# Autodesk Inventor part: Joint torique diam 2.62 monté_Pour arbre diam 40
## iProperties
Shininess: 64.0
Length Units: 11269
Angle Units: 11279
Time Units: 11290
Mass Units: 11283
Length Display Precision: 3
Angle Display Precision: 2
Compacted: True
Part Number: Joint torique diam 2.62 monté_Pour arbre diam 40
Document SubType Name: Modeling
Created: 2006-01
Material: Par défaut
Designer: riri
Density: 0.0
Volumn: 0.0
Area: 0.0
PropertySet Name: Model Information
Control State: 0
Master: False
Checked Out: False
Author: riri
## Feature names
1. Base1
